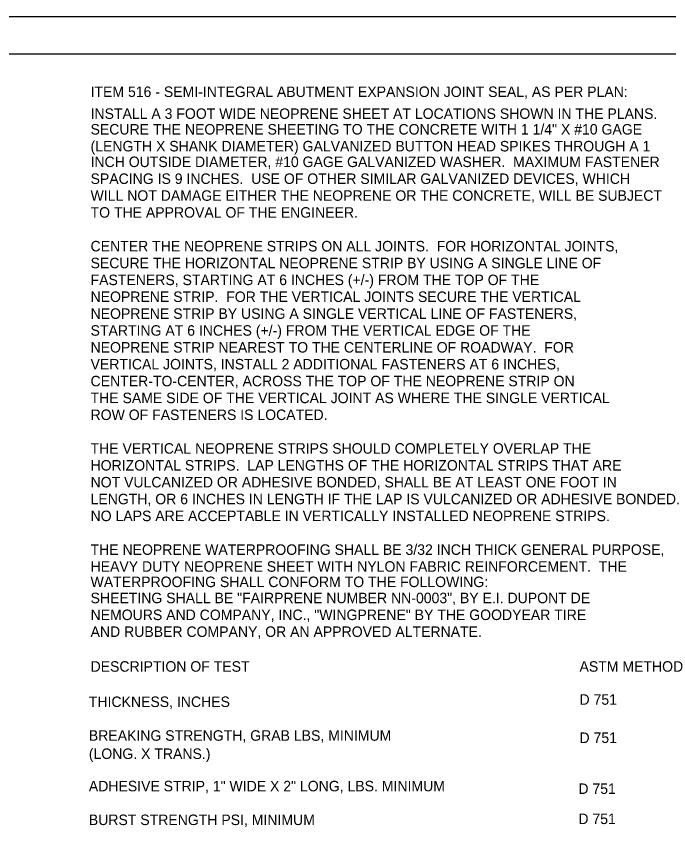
# Model space of a CAD drawing. Extents: x 0 to 34, y 0 to 22.
# Drawn here: x 20.84 to 29.54, y 11.04 to 22 of the extents above; entities that cross this region are included whole.
import ezdxf

# ---------------------------------------------------------------- set-up
doc = ezdxf.new("R2010")
doc.units = 0
for name, color, linetype in [('SH_Border', 7, 'Continuous'), ('SH_Cut_Line', 7, 'Continuous'), ('SH_Text', 7, 'Continuous')]:
    doc.layers.add(name, color=color, linetype=linetype)

msp = doc.modelspace()

# ---------------------------------------------------------------- linework, layer by layer
at = {"layer": 'SH_Border'}
msp.add_lwpolyline([(2, 21.5), (33.5, 21.5), (33.5, 0.5), (2, 0.5)], close=True, dxfattribs=at)
at = {"layer": 'SH_Cut_Line'}
msp.add_lwpolyline([(0, 22), (34, 22), (34, 0), (0, 0)], close=True, dxfattribs=at)

# ---------------------------------------------------------------- texts
at = {"layer": 'SH_Text'}
for s, p in [('ITEM 516 - SEMI-INTEGRAL ABUTMENT EXPANSION JOINT SEAL, AS PER PLAN:', (21.827, 20.925)), ('INSTALL A 3 FOOT WIDE NEOPRENE SHEET AT LOCATIONS SHOWN IN THE PLANS. ', (21.827, 20.633)), ('SECURE THE NEOPRENE SHEETING TO THE CONCRETE WITH 1 1/4" X #10 GAGE', (21.827, 20.424)), ('(LENGTH X SHANK DIAMETER) GALVANIZED BUTTON HEAD SPIKES THROUGH A 1', (21.827, 20.199)), ('INCH OUTSIDE DIAMETER, #10 GAGE GALVANIZED WASHER.  MAXIMUM FASTENER', (21.827, 19.99)), ('SPACING IS 9 INCHES.  USE OF OTHER SIMILAR GALVANIZED DEVICES, WHICH', (21.827, 19.765)), ('WILL NOT DAMAGE EITHER THE NEOPRENE OR THE CONCRETE, WILL BE SUBJECT', (21.827, 19.54)), ('TO THE APPROVAL OF THE ENGINEER. ', (21.827, 19.315)), ('CENTER THE NEOPRENE STRIPS ON ALL JOINTS.  FOR HORIZONTAL JOINTS,', (21.827, 18.865)), ('SECURE THE HORIZONTAL NEOPRENE STRIP BY USING A SINGLE LINE OF', (21.827, 18.64)), ('FASTENERS, STARTING AT 6 INCHES (+/-) FROM THE TOP OF THE', (21.827, 18.415)), ('NEOPRENE STRIP.  FOR THE VERTICAL JOINTS SECURE THE VERTICAL', (21.827, 18.19)), ('NEOPRENE STRIP BY USING A SINGLE VERTICAL LINE OF FASTENERS,', (21.827, 17.965)), ('STARTING AT 6 INCHES (+/-) FROM THE VERTICAL EDGE OF THE', (21.827, 17.74)), ('NEOPRENE STRIP NEAREST TO THE CENTERLINE OF ROADWAY.  FOR', (21.827, 17.515)), ('VERTICAL JOINTS, INSTALL 2 ADDITIONAL FASTENERS AT 6 INCHES,', (21.827, 17.29)), ('CENTER-TO-CENTER, ACROSS THE TOP OF THE NEOPRENE STRIP ON', (21.827, 17.065)), ('THE SAME SIDE OF THE VERTICAL JOINT AS WHERE THE SINGLE VERTICAL', (21.827, 16.84)), ('ROW OF FASTENERS IS LOCATED.', (21.827, 16.615)), ('THE VERTICAL NEOPRENE STRIPS SHOULD COMPLETELY OVERLAP THE', (21.827, 16.166)), ('HORIZONTAL STRIPS.  LAP LENGTHS OF THE HORIZONTAL STRIPS THAT ARE', (21.827, 15.941)), ('NOT VULCANIZED OR ADHESIVE BONDED, SHALL BE AT LEAST ONE FOOT IN', (21.827, 15.716)), ('LENGTH, OR 6 INCHES IN LENGTH IF THE LAP IS VULCANIZED OR ADHESIVE BONDED.', (21.827, 15.491)), ('NO LAPS ARE ACCEPTABLE IN VERTICALLY INSTALLED NEOPRENE STRIPS.', (21.827, 15.266)), ('THE NEOPRENE WATERPROOFING SHALL BE 3/32 INCH THICK GENERAL PURPOSE,', (21.827, 14.816)), ('HEAVY DUTY NEOPRENE SHEET WITH NYLON FABRIC REINFORCEMENT.  THE', (21.827, 14.591)), ('WATERPROOFING SHALL CONFORM TO THE FOLLOWING:', (21.827, 14.386)), ('SHEETING SHALL BE "FAIRPRENE NUMBER NN-0003", BY E.I. DUPONT DE', (21.827, 14.171)), ('NEMOURS AND COMPANY, INC., "WINGPRENE" BY THE GOODYEAR TIRE', (21.827, 13.946)), ('AND RUBBER COMPANY, OR AN APPROVED ALTERNATE. ', (21.827, 13.721)), ('DESCRIPTION OF TEST', (21.827, 13.257)), ('ASTM METHOD', (28.351, 13.257)), ('D 751', (28.351, 12.816)), ('THICKNESS, INCHES                                 ', (21.804, 12.786)), ('BREAKING STRENGTH, GRAB LBS, MINIMUM               ', (21.804, 12.336)), ('D 751', (28.351, 12.306)), ('(LONG. X TRANS.)', (21.804, 12.093)), ('ADHESIVE STRIP, 1" WIDE X 2" LONG, LBS. MINIMUM     ', (21.804, 11.661)), ('D 751', (28.336, 11.626)), ('BURST STRENGTH PSI, MINIMUM                       ', (21.804, 11.211)), ('D 751', (28.336, 11.224))]:
    msp.add_text(s, height=0.14, dxfattribs=at).set_placement(p)

doc.saveas('drawing.dxf')
